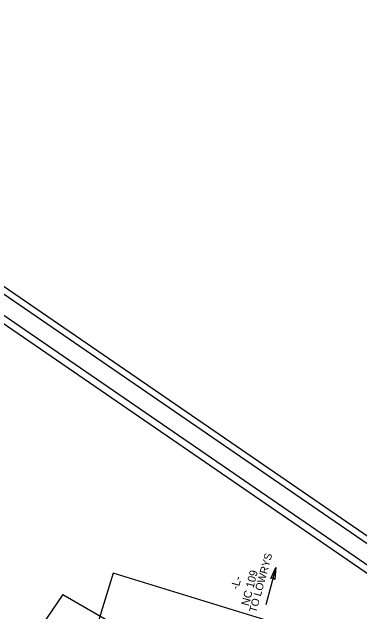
# Model space of a CAD drawing. Extents: x 1638787 to 1643250, y 391480 to 396306.
# Drawn here: x 1641773 to 1642368, y 395279 to 396306 of the extents above; entities that cross this region are included whole.
import ezdxf

# ---------------------------------------------------------------- set-up
doc = ezdxf.new("R2010")
doc.units = 0
for name, color, linetype in [('Old_Level_1', 7, 'Continuous'), ('Prop Terminator CELL', 7, 'Continuous'), ('Sheet Plan Layout CELL', 7, 'Continuous'), ('Sheet Plot Border Inside CELL', 7, 'Continuous'), ('Sheet Plot Border Outside CELL', 7, 'Continuous'), ('UC Title Plan Sheet 34 CELL', 7, 'Continuous')]:
    doc.layers.add(name, color=color, linetype=linetype)

msp = doc.modelspace()

# ---------------------------------------------------------------- linework, layer by layer
at = {"layer": 'Old_Level_1'}
for p, q in [((1642225.7, 395354.9), (1642208.1, 395291.3)), ((1641860.2, 395308.7), (1641593.3, 394919.4)), ((1641860.2, 395308.7), (1642122.8, 395158.2))]:
    msp.add_line(p, q, dxfattribs=at)
at = {"layer": 'Prop Terminator CELL'}
msp.add_lwpolyline([(1642217, 395336.4), (1642225.7, 395354.9), (1642223.8, 395334.4), (1642221, 395337.9)], close=True, dxfattribs=at)
at = {"layer": 'Sheet Plan Layout CELL'}
msp.add_lwpolyline([(1642171.6, 394648.6), (1642348, 395222.1), (1641946.6, 395345.6), (1641784.3, 394818.2)], close=True, dxfattribs=at)
at = {"layer": 'Sheet Plot Border Inside CELL'}
msp.add_lwpolyline([(1640937.7, 391536.4), (1643199.6, 394834.9), (1641111.3, 396267), (1638849.3, 392968.5)], close=True, dxfattribs=at)
at = {"layer": 'Sheet Plot Border Outside CELL'}
msp.add_lwpolyline([(1641072.9, 396306.4), (1638787.2, 392973.3), (1640964.4, 391480.2), (1643250.2, 394813.4)], close=True, dxfattribs=at)
at = {"layer": 'UC Title Plan Sheet 34 CELL'}
for points in [[(1643157.8, 394827.3), (1641119.1, 396225.3)], [(1642775, 395075.2), (1641122.2, 396208.6)]]:
    msp.add_lwpolyline(points, dxfattribs=at)

# ---------------------------------------------------------------- texts
at = {"layer": 'Old_Level_1'}
for s, height, rotation, p in [('TO LOWRYS', 13, 74.5497, (1642191.8, 395277)), ('NC 109', 13.71, 75.2453, (1642179, 395288.4)), ('-L-', 13.71, 75.2453, (1642161.2, 395316.5))]:
    msp.add_text(s, height=height, rotation=rotation, dxfattribs=at).set_placement(p)

doc.saveas('drawing.dxf')
